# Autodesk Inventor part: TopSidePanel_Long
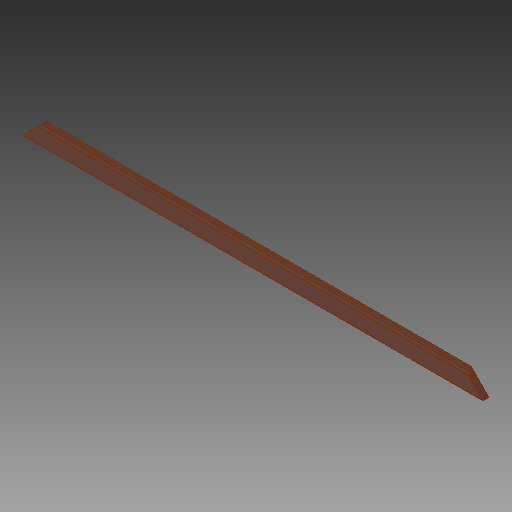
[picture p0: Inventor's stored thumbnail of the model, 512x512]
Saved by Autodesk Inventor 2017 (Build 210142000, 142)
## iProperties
Created: 2017-05
Part Number: TopSidePanel_Long
Material: Generic
Document SubType Name: Modeling
Designer: Savy
Density: 1 g/cm^3
Appearance: Default
Author: Savy
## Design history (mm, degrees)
feature "SOLID1"
body "Solid1"
